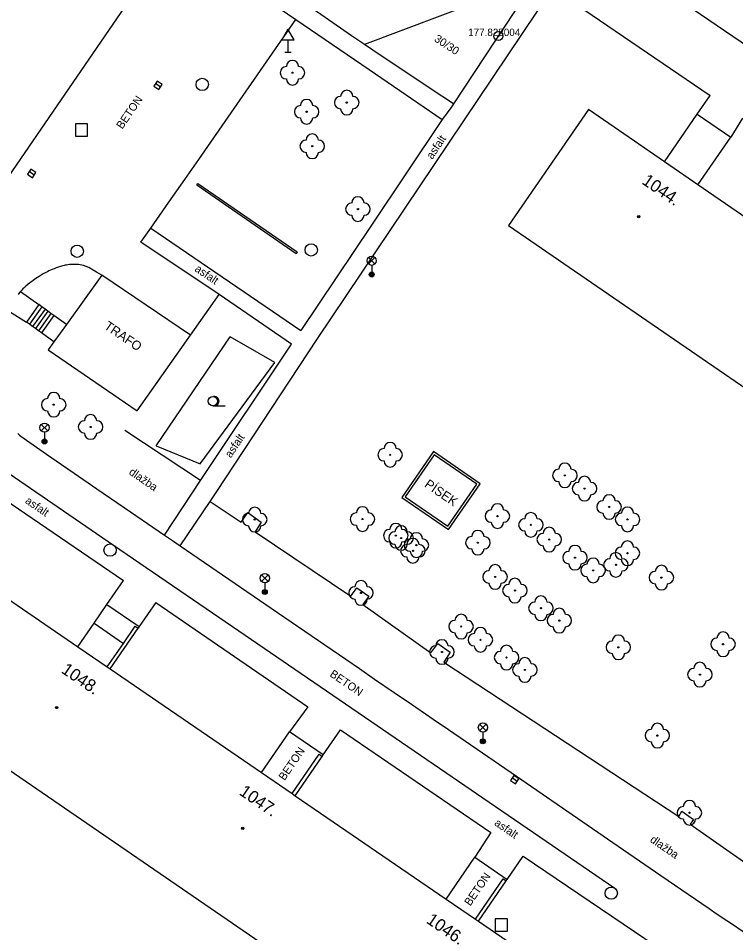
# Model space of a CAD drawing. Extents: x -539515 to -538098, y -1182060 to -1180157.
# Drawn here: x -538687.3 to -538629, y -1181340.3 to -1181266 of the extents above; entities that cross this region are included whole.
import ezdxf

# ---------------------------------------------------------------- set-up
doc = ezdxf.new("R2010")
doc.units = 0
for name, color, linetype in [('Vrstva 10', 7, 'Continuous'), ('Vrstva 11', 7, 'Continuous'), ('Vrstva 21', 7, 'Continuous'), ('Vrstva 22', 7, 'Continuous'), ('Vrstva 23', 7, 'Continuous'), ('Vrstva 26', 7, 'Continuous'), ('Vrstva 27', 7, 'Continuous'), ('Vrstva 33', 7, 'Continuous'), ('Vrstva 34', 7, 'Continuous'), ('Vrstva 36', 7, 'Continuous'), ('Vrstva 39', 7, 'Continuous'), ('Vrstva 40', 7, 'Continuous'), ('Vrstva 41', 7, 'Continuous'), ('Vrstva 47', 7, 'Continuous'), ('Vrstva 5', 7, 'Continuous'), ('Vrstva 7', 7, 'Continuous')]:
    doc.layers.add(name, color=color, linetype=linetype)

msp = doc.modelspace()

# ---------------------------------------------------------------- linework, layer by layer
at = {"layer": 'Vrstva 10'}
for p, q in [((-538634.64, -1181263.75), (-538621.575, -1181272.74)), ((-538672.638, -1181277.498), (-538664.76, -1181266.12)), ((-538670.97, -1181288.48), (-538677.35, -1181284.23)), ((-538673.32, -1181291.77), (-538670.97, -1181288.48)), ((-538696.576, -1181297.176), (-538679.57, -1181308.82)), ((-538653.55, -1181301.22), (-538656.129, -1181304.952)), ((-538653.499, -1181301.498), (-538655.851, -1181304.901)), ((-538649.76, -1181303.84), (-538653.55, -1181301.22)), ((-538650.037, -1181303.89), (-538653.499, -1181301.498)), ((-538652.338, -1181307.571), (-538649.76, -1181303.84)), ((-538652.389, -1181307.293), (-538650.037, -1181303.89)), ((-538656.129, -1181304.952), (-538652.338, -1181307.571)), ((-538655.851, -1181304.901), (-538652.389, -1181307.293)), ((-538679.57, -1181308.82), (-538669.384, -1181315.789)), ((-538674.15, -1181308.89), (-538666.245, -1181314.3)), ((-538669.384, -1181315.789), (-538654.102, -1181326.24)), ((-538654.102, -1181326.24), (-538638.82, -1181336.69)), ((-538646.81, -1181327.61), (-538638.982, -1181332.988))]:
    msp.add_line(p, q, dxfattribs=at)
for points in [[(-538677.35, -1181284.23), (-538676.944, -1181283.661), (-538676.54, -1181283.09), (-538675.059, -1181280.975), (-538673.766, -1181279.122), (-538672.638, -1181277.498)], [(-538680.53, -1181286.91), (-538680.944, -1181286.656), (-538681.358, -1181286.402), (-538681.432, -1181286.358), (-538681.505, -1181286.318), (-538681.578, -1181286.281), (-538681.651, -1181286.248), (-538681.723, -1181286.217), (-538681.795, -1181286.189), (-538681.866, -1181286.163), (-538681.937, -1181286.14), (-538682.007, -1181286.12), (-538682.147, -1181286.085), (-538682.284, -1181286.059), (-538682.418, -1181286.04), (-538682.549, -1181286.028), (-538682.677, -1181286.021), (-538682.802, -1181286.02), (-538682.924, -1181286.023), (-538683.043, -1181286.031), (-538683.159, -1181286.042), (-538683.272, -1181286.057), (-538683.382, -1181286.074), (-538683.488, -1181286.093), (-538683.592, -1181286.115), (-538683.692, -1181286.139), (-538683.79, -1181286.164), (-538683.884, -1181286.191), (-538684.067, -1181286.248), (-538684.239, -1181286.308), (-538684.4, -1181286.37), (-538684.551, -1181286.433), (-538684.692, -1181286.496), (-538684.824, -1181286.559), (-538684.947, -1181286.62), (-538685.062, -1181286.68), (-538685.276, -1181286.798), (-538685.461, -1181286.908), (-538685.622, -1181287.008), (-538685.761, -1181287.099), (-538685.882, -1181287.18), (-538686.09, -1181287.328), (-538686.244, -1181287.442), (-538686.358, -1181287.529), (-538686.526, -1181287.663), (-538686.69, -1181287.8), (-538686.756, -1181287.857), (-538686.817, -1181287.912), (-538686.931, -1181288.02), (-538687.031, -1181288.123), (-538687.119, -1181288.22), (-538687.198, -1181288.312), (-538687.267, -1181288.399), (-538687.33, -1181288.481)], [(-538687.358, -1181299.762), (-538687.297, -1181299.817), (-538687.2, -1181299.895), (-538687.1, -1181299.97), (-538686.371, -1181300.484), (-538685.004, -1181301.44), (-538683.808, -1181302.271), (-538682.761, -1181302.995)], [(-538682.761, -1181302.995), (-538680.927, -1181304.255), (-538678.175, -1181306.137), (-538675.42, -1181308.02), (-538674.785, -1181308.455)], [(-538674.785, -1181308.455), (-538674.15, -1181308.89)], [(-538666.245, -1181314.3), (-538659.578, -1181318.863)], [(-538659.578, -1181318.863), (-538658.34, -1181319.71)], [(-538658.34, -1181319.71), (-538656.752, -1181320.795), (-538655.345, -1181321.754), (-538653.847, -1181322.776), (-538653.589, -1181322.954), (-538652.35, -1181323.8)], [(-538652.35, -1181323.8), (-538649.579, -1181325.704), (-538646.81, -1181327.61)], [(-538638.982, -1181332.988), (-538635.067, -1181335.675), (-538631.15, -1181338.36)], [(-538631.15, -1181338.36), (-538630.571, -1181338.752), (-538629.7, -1181339.334), (-538629.264, -1181339.626), (-538628.83, -1181339.92), (-538624.923, -1181342.589)]]:
    msp.add_lwpolyline(points, dxfattribs=at)
at = {"layer": 'Vrstva 11'}
for p, q in [((-538669.745, -1181262.72), (-538664.76, -1181266.12)), ((-538645.21, -1181262.81), (-538648.565, -1181267.895)), ((-538642.6, -1181264.43), (-538636.84, -1181268.37)), ((-538650.31, -1181264.84), (-538659.17, -1181268.16)), ((-538664.76, -1181266.12), (-538658.8, -1181270.19)), ((-538648.565, -1181267.895), (-538651.92, -1181272.98)), ((-538636.84, -1181268.37), (-538631.08, -1181272.31)), ((-538658.8, -1181270.19), (-538652.84, -1181274.26)), ((-538632.114, -1181273.816), (-538631.08, -1181272.31)), ((-538652.84, -1181274.26), (-538658.59, -1181282.83)), ((-538628.43, -1181274.15), (-538629.4, -1181275.68)), ((-538658.59, -1181282.83), (-538664.34, -1181291.4)), ((-538676.54, -1181283.09), (-538664.34, -1181291.4)), ((-538687.119, -1181288.22), (-538685.64, -1181289.29)), ((-538665.1, -1181292.51), (-538670.97, -1181288.48)), ((-538685.64, -1181289.29), (-538686.64, -1181290.71)), ((-538685.382, -1181289.475), (-538686.396, -1181290.885)), ((-538685.138, -1181289.65), (-538686.152, -1181291.06)), ((-538688.02, -1181289.85), (-538686.64, -1181290.71)), ((-538684.895, -1181289.825), (-538685.909, -1181291.235)), ((-538684.651, -1181290), (-538685.665, -1181291.41)), ((-538684.408, -1181290.175), (-538685.422, -1181291.585)), ((-538672.49, -1181303.59), (-538678.657, -1181299.511)), ((-538690.92, -1181303.4), (-538678.77, -1181311.7)), ((-538671.707, -1181305.275), (-538669.196, -1181306.972)), ((-538668.06, -1181307.74), (-538660.29, -1181312.97)), ((-538658.81, -1181312.97), (-538659.291, -1181313.663)), ((-538680.104, -1181313.648), (-538677.475, -1181315.449)), ((-538676.14, -1181313.5), (-538663.78, -1181321.97)), ((-538659.291, -1181313.663), (-538653.78, -1181317.59)), ((-538652.73, -1181318.33), (-538633.61, -1181330.87)), ((-538663.78, -1181321.97), (-538665.27, -1181323.99)), ((-538661.13, -1181323.83), (-538648.91, -1181332.17)), ((-538667.542, -1181327.306), (-538665.27, -1181323.99)), ((-538662.527, -1181325.869), (-538665.27, -1181323.99)), ((-538632.69, -1181331.5), (-538606.03, -1181350.16)), ((-538648.91, -1181332.17), (-538650.2, -1181334.18)), ((-538652.533, -1181337.586), (-538650.2, -1181334.18)), ((-538650.2, -1181334.18), (-538647.568, -1181335.981)), ((-538646.28, -1181334.1), (-538634.05, -1181342.34))]:
    msp.add_line(p, q, dxfattribs=at)
for points in [[(-538660.213, -1181267.449), (-538661.123, -1181266.823), (-538662.712, -1181265.723), (-538665.09, -1181264.066), (-538666.279, -1181263.237), (-538667.47, -1181262.41)], [(-538663.02, -1181292.1), (-538643.94, -1181263.7)], [(-538651.92, -1181272.98), (-538653.735, -1181271.778), (-538656.458, -1181269.978), (-538657.816, -1181269.072), (-538658.494, -1181268.617), (-538659.17, -1181268.16), (-538660.213, -1181267.449)], [(-538651.92, -1181272.98), (-538652.031, -1181273.143), (-538652.13, -1181273.284), (-538652.309, -1181273.527), (-538652.579, -1181273.89), (-538652.711, -1181274.074), (-538652.84, -1181274.26)], [(-538683.401, -1181290.901), (-538684.408, -1181290.175), (-538684.651, -1181290), (-538684.895, -1181289.825), (-538685.138, -1181289.65), (-538685.382, -1181289.475), (-538685.64, -1181289.29)], [(-538684.415, -1181292.31), (-538685.422, -1181291.585), (-538685.665, -1181291.41), (-538685.909, -1181291.235), (-538686.152, -1181291.06), (-538686.396, -1181290.885), (-538686.64, -1181290.71)], [(-538672.49, -1181303.59), (-538665.1, -1181292.51)], [(-538671.17, -1181304.48), (-538663.02, -1181292.1)], [(-538675.42, -1181308.02), (-538672.49, -1181303.59)], [(-538674.15, -1181308.89), (-538671.707, -1181305.275), (-538671.17, -1181304.48)], [(-538669.196, -1181306.972), (-538668.66, -1181306.18), (-538667.56, -1181306.97), (-538668.06, -1181307.74)], [(-538681.15, -1181315.18), (-538680.104, -1181313.648), (-538678.77, -1181311.7)], [(-538660.29, -1181312.97), (-538659.79, -1181312.29), (-538658.81, -1181312.97)], [(-538676.14, -1181313.5), (-538677.475, -1181315.449), (-538677.56, -1181315.573)], [(-538653.78, -1181317.59), (-538653.21, -1181316.81), (-538652.19, -1181317.53), (-538652.73, -1181318.33)], [(-538662.611, -1181325.992), (-538662.527, -1181325.869), (-538661.13, -1181323.83)], [(-538633.61, -1181330.87), (-538633.36, -1181330.45), (-538632.41, -1181331.11), (-538632.69, -1181331.5)], [(-538647.653, -1181336.105), (-538647.568, -1181335.981), (-538646.28, -1181334.1)]]:
    msp.add_lwpolyline(points, dxfattribs=at)
at = {"layer": 'Vrstva 21'}
for p, q in [((-538676.09, -1181300.75), (-538670.086, -1181291.901)), ((-538666.46, -1181293.99), (-538670.086, -1181291.901)), ((-538672.53, -1181302.22), (-538666.46, -1181293.99)), ((-538676.09, -1181300.75), (-538672.53, -1181302.22))]:
    msp.add_line(p, q, dxfattribs=at)
for radius in [0.375, 0.375, 0.05, 0.05]:
    msp.add_circle((-538648.29, -1181267.47), radius, dxfattribs=at)
at = {"layer": 'Vrstva 22'}
for centre in [(-538665.02, -1181270.45), (-538660.61, -1181272.88), (-538663.87, -1181273.62), (-538663.41, -1181276.42), (-538659.7, -1181281.53), (-538684.43, -1181297.42), (-538681.43, -1181299.23), (-538657.08, -1181301.49), (-538642.88, -1181303.16), (-538641.28, -1181304.24), (-538639.28, -1181305.73), (-538668.09, -1181306.75), (-538659.33, -1181306.71), (-538648.36, -1181306.47), (-538637.787, -1181306.736), (-538645.64, -1181307.18), (-538656.62, -1181308.06), (-538656.19, -1181308.25), (-538654.95, -1181308.83), (-538649.95, -1181308.63), (-538644.15, -1181308.38), (-538655.23, -1181309.29), (-538637.79, -1181309.49), (-538642.055, -1181309.847), (-538638.73, -1181310.43), (-538640.58, -1181310.88), (-538648.548, -1181311.416), (-538635.03, -1181311.47), (-538659.45, -1181312.71), (-538646.94, -1181312.52), (-538644.822, -1181313.952), (-538643.33, -1181314.96), (-538651.311, -1181315.441), (-538649.74, -1181316.52), (-538638.53, -1181317.13), (-538630.02, -1181316.88), (-538652.87, -1181317.51), (-538647.62, -1181317.959), (-538646.13, -1181318.97), (-538631.9, -1181319.35), (-538635.36, -1181324.3), (-538632.75, -1181330.57)]:
    msp.add_circle(centre, 0.05, dxfattribs=at)
for centre, start, end in [((-538665.02, -1181269.95), 0, 180), ((-538665.52, -1181270.45), 90, 270), ((-538664.52, -1181270.45), 270, 90), ((-538665.02, -1181270.95), 180, 0), ((-538660.61, -1181272.38), 0, 180), ((-538663.87, -1181273.12), 0, 180), ((-538661.11, -1181272.88), 90, 270), ((-538660.11, -1181272.88), 270, 90), ((-538664.37, -1181273.62), 90, 270), ((-538663.37, -1181273.62), 270, 90), ((-538660.61, -1181273.38), 180, 0), ((-538663.87, -1181274.12), 180, 0), ((-538663.41, -1181275.92), 0, 180), ((-538663.91, -1181276.42), 90, 270), ((-538662.91, -1181276.42), 270, 90), ((-538663.41, -1181276.92), 180, 0), ((-538659.7, -1181281.03), 0, 180), ((-538660.2, -1181281.53), 90, 270), ((-538659.2, -1181281.53), 270, 90), ((-538659.7, -1181282.03), 180, 0), ((-538684.93, -1181297.42), 90, 270), ((-538684.43, -1181296.92), 0, 180), ((-538683.93, -1181297.42), 270, 90), ((-538684.43, -1181297.92), 180, 0), ((-538681.43, -1181298.73), 0, 180), ((-538681.93, -1181299.23), 90, 270), ((-538680.93, -1181299.23), 270, 90), ((-538681.43, -1181299.73), 180, 0), ((-538657.08, -1181300.99), 0, 180), ((-538657.58, -1181301.49), 90, 270), ((-538656.58, -1181301.49), 270, 90), ((-538657.08, -1181301.99), 180, 0), ((-538642.88, -1181302.66), 0, 180), ((-538643.38, -1181303.16), 90, 270), ((-538642.38, -1181303.16), 270, 90), ((-538642.88, -1181303.66), 180, 0), ((-538641.78, -1181304.24), 90, 270), ((-538641.28, -1181303.74), 0, 180), ((-538640.78, -1181304.24), 270, 90), ((-538641.28, -1181304.74), 180, 0), ((-538639.78, -1181305.73), 90, 270), ((-538639.28, -1181305.23), 0, 180), ((-538638.78, -1181305.73), 270, 90), ((-538668.09, -1181306.25), 0, 180), ((-538659.33, -1181306.21), 0, 180), ((-538648.86, -1181306.47), 90, 270), ((-538648.36, -1181305.97), 0, 180), ((-538647.86, -1181306.47), 270, 90), ((-538637.787, -1181306.236), 0, 180), ((-538668.59, -1181306.75), 90, 270), ((-538667.59, -1181306.75), 270, 90), ((-538659.83, -1181306.71), 90, 270), ((-538658.83, -1181306.71), 270, 90), ((-538646.14, -1181307.18), 90, 270), ((-538645.64, -1181306.68), 0, 180), ((-538645.14, -1181307.18), 270, 90), ((-538639.28, -1181306.23), 180, 0), ((-538638.287, -1181306.736), 90, 270), ((-538637.287, -1181306.736), 270, 90), ((-538668.09, -1181307.25), 180, 0), ((-538659.33, -1181307.21), 180, 0), ((-538656.62, -1181307.56), 0, 180), ((-538656.19, -1181307.75), 0, 180), ((-538648.36, -1181306.97), 180, 0), ((-538644.15, -1181307.88), 0, 180), ((-538637.787, -1181307.236), 180, 0), ((-538657.12, -1181308.06), 90, 270), ((-538656.69, -1181308.25), 90, 270), ((-538656.12, -1181308.06), 270, 90), ((-538655.23, -1181308.79), 0, 180), ((-538655.69, -1181308.25), 270, 90), ((-538654.95, -1181308.33), 0, 180), ((-538650.45, -1181308.63), 90, 270), ((-538649.95, -1181308.13), 0, 180), ((-538649.45, -1181308.63), 270, 90), ((-538645.64, -1181307.68), 180, 0), ((-538644.65, -1181308.38), 90, 270), ((-538643.65, -1181308.38), 270, 90), ((-538656.62, -1181308.56), 180, 0), ((-538656.19, -1181308.75), 180, 0), ((-538655.73, -1181309.29), 90, 270), ((-538655.45, -1181308.83), 90, 270), ((-538654.73, -1181309.29), 270, 90), ((-538654.45, -1181308.83), 270, 90), ((-538644.15, -1181308.88), 180, 0), ((-538642.055, -1181309.347), 0, 180), ((-538638.29, -1181309.49), 90, 270), ((-538637.79, -1181308.99), 0, 180), ((-538637.29, -1181309.49), 270, 90), ((-538654.95, -1181309.33), 180, 0), ((-538649.95, -1181309.13), 180, 0), ((-538642.555, -1181309.847), 90, 270), ((-538641.555, -1181309.847), 270, 90), ((-538638.73, -1181309.93), 0, 180), ((-538655.23, -1181309.79), 180, 0), ((-538648.548, -1181310.916), 0, 180), ((-538642.055, -1181310.347), 180, 0), ((-538641.08, -1181310.88), 90, 270), ((-538640.58, -1181310.38), 0, 180), ((-538640.08, -1181310.88), 270, 90), ((-538639.23, -1181310.43), 90, 270), ((-538637.79, -1181309.99), 180, 0), ((-538638.23, -1181310.43), 270, 90), ((-538635.03, -1181310.97), 0, 180), ((-538649.048, -1181311.416), 90, 270), ((-538648.048, -1181311.416), 270, 90), ((-538638.73, -1181310.93), 180, 0), ((-538635.53, -1181311.47), 90, 270), ((-538634.53, -1181311.47), 270, 90), ((-538659.45, -1181312.21), 0, 180), ((-538648.548, -1181311.916), 180, 0), ((-538646.94, -1181312.02), 0, 180), ((-538640.58, -1181311.38), 180, 0), ((-538635.03, -1181311.97), 180, 0), ((-538659.95, -1181312.71), 90, 270), ((-538658.95, -1181312.71), 270, 90), ((-538647.44, -1181312.52), 90, 270), ((-538646.44, -1181312.52), 270, 90), ((-538659.45, -1181313.21), 180, 0), ((-538646.94, -1181313.02), 180, 0), ((-538645.322, -1181313.952), 90, 270), ((-538644.822, -1181313.452), 0, 180), ((-538644.322, -1181313.952), 270, 90), ((-538643.33, -1181314.46), 0, 180), ((-538651.811, -1181315.441), 90, 270), ((-538651.311, -1181314.941), 0, 180), ((-538650.811, -1181315.441), 270, 90), ((-538644.822, -1181314.452), 180, 0), ((-538643.83, -1181314.96), 90, 270), ((-538642.83, -1181314.96), 270, 90), ((-538649.74, -1181316.02), 0, 180), ((-538643.33, -1181315.46), 180, 0), ((-538651.311, -1181315.941), 180, 0), ((-538650.24, -1181316.52), 90, 270), ((-538649.24, -1181316.52), 270, 90), ((-538638.53, -1181316.63), 0, 180), ((-538630.52, -1181316.88), 90, 270), ((-538630.02, -1181316.38), 0, 180), ((-538629.52, -1181316.88), 270, 90), ((-538653.37, -1181317.51), 90, 270), ((-538652.87, -1181317.01), 0, 180), ((-538652.37, -1181317.51), 270, 90), ((-538649.74, -1181317.02), 180, 0), ((-538647.62, -1181317.459), 0, 180), ((-538639.03, -1181317.13), 90, 270), ((-538638.03, -1181317.13), 270, 90), ((-538648.12, -1181317.959), 90, 270), ((-538647.12, -1181317.959), 270, 90), ((-538638.53, -1181317.63), 180, 0), ((-538630.02, -1181317.38), 180, 0), ((-538652.87, -1181318.01), 180, 0), ((-538647.62, -1181318.459), 180, 0), ((-538646.63, -1181318.97), 90, 270), ((-538646.13, -1181318.47), 0, 180), ((-538645.63, -1181318.97), 270, 90), ((-538631.9, -1181318.85), 0, 180), ((-538632.4, -1181319.35), 90, 270), ((-538631.4, -1181319.35), 270, 90), ((-538646.13, -1181319.47), 180, 0), ((-538631.9, -1181319.85), 180, 0), ((-538635.86, -1181324.3), 90, 270), ((-538635.36, -1181323.8), 0, 180), ((-538634.86, -1181324.3), 270, 90), ((-538635.36, -1181324.8), 180, 0), ((-538632.75, -1181330.07), 0, 180), ((-538633.25, -1181330.57), 90, 270), ((-538632.25, -1181330.57), 270, 90), ((-538632.75, -1181331.07), 180, 0)]:
    msp.add_arc(centre, 0.5, start, end, dxfattribs=at)
at = {"layer": 'Vrstva 26'}
for points in [[(-538682.67, -1181275.61), (-538681.67, -1181275.61), (-538681.67, -1181274.61), (-538682.67, -1181274.61)], [(-538648.54, -1181340.19), (-538647.54, -1181340.19), (-538647.54, -1181339.19), (-538648.54, -1181339.19)]]:
    msp.add_lwpolyline(points, close=True, dxfattribs=at)
at = {"layer": 'Vrstva 27'}
for p, q in [((-538675.744, -1181271.621), (-538676.156, -1181271.339)), ((-538686.014, -1181278.771), (-538686.426, -1181278.489)), ((-538646.753, -1181328.024), (-538647.165, -1181327.742))]:
    msp.add_line(p, q, dxfattribs=at)
for points in [[(-538675.602, -1181271.415), (-538676.015, -1181271.132), (-538676.298, -1181271.545), (-538675.885, -1181271.828)], [(-538685.872, -1181278.565), (-538686.285, -1181278.282), (-538686.568, -1181278.695), (-538686.155, -1181278.978)], [(-538646.611, -1181327.818), (-538647.024, -1181327.535), (-538647.307, -1181327.948), (-538646.894, -1181328.231)]]:
    msp.add_lwpolyline(points, close=True, dxfattribs=at)
for centre in [(-538672.35, -1181271.4), (-538682.52, -1181284.96), (-538663.5, -1181284.85), (-538679.853, -1181309.233), (-538639.103, -1181337.103)]:
    msp.add_circle(centre, 0.5, dxfattribs=at)
at = {"layer": 'Vrstva 33'}
for p, q in [((-538658.845, -1181285.99), (-538658.315, -1181285.46)), ((-538658.845, -1181285.46), (-538658.315, -1181285.99)), ((-538658.58, -1181286.1), (-538658.58, -1181286.85)), ((-538685.445, -1181299.55), (-538684.915, -1181299.02)), ((-538685.445, -1181299.02), (-538684.915, -1181299.55)), ((-538685.18, -1181299.66), (-538685.18, -1181300.41)), ((-538667.535, -1181311.78), (-538667.005, -1181311.25)), ((-538667.535, -1181311.25), (-538667.005, -1181311.78)), ((-538667.27, -1181311.89), (-538667.27, -1181312.64)), ((-538649.805, -1181323.91), (-538649.275, -1181323.38)), ((-538649.805, -1181323.38), (-538649.275, -1181323.91)), ((-538649.54, -1181324.02), (-538649.54, -1181324.77))]:
    msp.add_line(p, q, dxfattribs=at)
for centre, radius in [((-538658.58, -1181285.725), 0.375), ((-538658.58, -1181286.85), 0.2), ((-538658.58, -1181286.85), 0.145), ((-538658.58, -1181286.85), 0.0876), ((-538685.18, -1181299.285), 0.375), ((-538685.18, -1181300.41), 0.2), ((-538685.18, -1181300.41), 0.145), ((-538685.18, -1181300.41), 0.0876), ((-538667.27, -1181311.515), 0.375), ((-538667.27, -1181312.64), 0.2), ((-538667.27, -1181312.64), 0.145), ((-538667.27, -1181312.64), 0.0876), ((-538649.54, -1181323.645), 0.375), ((-538649.54, -1181324.77), 0.2), ((-538649.54, -1181324.77), 0.145), ((-538649.54, -1181324.77), 0.0876)]:
    msp.add_circle(centre, radius, dxfattribs=at)
at = {"layer": 'Vrstva 34'}
for p, q in [((-538665.389, -1181267.767), (-538665.389, -1181268.785)), ((-538665.639, -1181268.785), (-538665.139, -1181268.785))]:
    msp.add_line(p, q, dxfattribs=at)
msp.add_lwpolyline([(-538665.889, -1181267.767), (-538664.889, -1181267.767), (-538665.389, -1181266.901)], close=True, dxfattribs=at)
at = {"layer": 'Vrstva 36'}
msp.add_line((-538671.491, -1181297.51), (-538670.491, -1181297.51), dxfattribs=at)
msp.add_circle((-538671.491, -1181297.135), 0.375, dxfattribs=at)
msp.add_arc((-538671.366, -1181297.135), 0.375, 260.40593, 99.59406, dxfattribs=at)
at = {"layer": 'Vrstva 39'}
for centre, radius in [((-538636.878, -1181282.148), 0.09), ((-538636.878, -1181282.148), 0.0398), ((-538684.195, -1181322.024), 0.09), ((-538684.195, -1181322.024), 0.0398), ((-538669.062, -1181331.834), 0.09), ((-538669.062, -1181331.834), 0.0398)]:
    msp.add_circle(centre, radius, dxfattribs=at)
at = {"layer": 'Vrstva 5'}
for p, q in [((-538640.97, -1181273.45), (-538647.45, -1181282.86)), ((-538634.782, -1181277.7), (-538632.114, -1181273.816)), ((-538632.114, -1181273.816), (-538629.4, -1181275.68)), ((-538632.068, -1181279.564), (-538629.4, -1181275.68)), ((-538673.32, -1181291.77), (-538680.53, -1181286.91)), ((-538677.64, -1181297.93), (-538673.32, -1181291.77)), ((-538684.89, -1181292.97), (-538677.64, -1181297.93)), ((-538724.84, -1181301.89), (-538635.14, -1181363.33)), ((-538682.46, -1181317.088), (-538681.15, -1181315.18)), ((-538681.15, -1181315.18), (-538678.77, -1181316.81))]:
    msp.add_line(p, q, dxfattribs=at)
for points in [[(-538674.73, -1181259.32), (-538689.745, -1181281.25)], [(-538634.782, -1181277.7), (-538640.97, -1181273.45)], [(-538632.068, -1181279.564), (-538634.782, -1181277.7)], [(-538620.033, -1181287.83), (-538632.068, -1181279.564)], [(-538647.45, -1181282.86), (-538548.42, -1181350.836)], [(-538680.53, -1181286.91), (-538683.401, -1181290.901)], [(-538683.401, -1181290.901), (-538684.415, -1181292.31)], [(-538684.415, -1181292.31), (-538684.89, -1181292.97)], [(-538694.6, -1181308.773), (-538682.46, -1181317.088)], [(-538682.46, -1181317.088), (-538680.078, -1181318.719)], [(-538680.078, -1181318.719), (-538679.831, -1181318.889)], [(-538679.831, -1181318.889), (-538667.542, -1181327.306)], [(-538667.542, -1181327.306), (-538665.045, -1181329.015)], [(-538665.045, -1181329.015), (-538664.798, -1181329.185)], [(-538664.798, -1181329.185), (-538652.533, -1181337.586)], [(-538652.533, -1181337.586), (-538650.149, -1181339.218)], [(-538650.149, -1181339.218), (-538649.902, -1181339.388)], [(-538649.902, -1181339.388), (-538637.736, -1181347.722)]]:
    msp.add_lwpolyline(points, dxfattribs=at)
at = {"layer": 'Vrstva 7'}
for p, q in [((-538672.8, -1181279.57), (-538664.72, -1181285.13)), ((-538679.831, -1181318.889), (-538677.56, -1181315.573)), ((-538664.798, -1181329.185), (-538662.611, -1181325.992)), ((-538649.902, -1181339.388), (-538647.653, -1181336.105))]:
    msp.add_line(p, q, dxfattribs=at)
for points in [[(-538672.8, -1181279.57), (-538672.715, -1181279.446)], [(-538672.715, -1181279.446), (-538664.635, -1181285.006)], [(-538664.635, -1181285.006), (-538664.72, -1181285.13)], [(-538680.078, -1181318.719), (-538678.77, -1181316.81), (-538677.807, -1181315.404), (-538677.56, -1181315.573)], [(-538665.045, -1181329.015), (-538662.858, -1181325.823), (-538662.611, -1181325.992)], [(-538650.149, -1181339.218), (-538647.901, -1181335.935), (-538647.653, -1181336.105)]]:
    msp.add_lwpolyline(points, dxfattribs=at)

# ---------------------------------------------------------------- texts
at = {"layer": 'Vrstva 22'}
msp.add_text('177.82 ', height=0.6, dxfattribs=at).set_placement((-538650.741, -1181267.47))
at = {"layer": 'Vrstva 23'}
msp.add_text('8004', height=0.6, dxfattribs=at).set_placement((-538648.29, -1181267.47))
at = {"layer": 'Vrstva 40'}
for s, rotation, p in [('30/30', 326.55021, (-538653.558, -1181267.846)), ('BETON', 55.60171, (-538678.862, -1181275.081)), ('asfalt', 56.23685, (-538653.654, -1181277.53)), ('asfalt', 325.73936, (-538673.022, -1181286.521)), ('asfalt', 56.23685, (-538670.034, -1181301.793)), ('dlažba', 325.6045, (-538678.373, -1181303.027)), ('asfalt', 325.66194, (-538686.809, -1181305.365)), ('BETON', 325.63485, (-538662.046, -1181319.44)), ('BETON', 55.59526, (-538665.665, -1181328.001)), ('asfalt', 325.63535, (-538648.672, -1181331.535)), ('dlažba', 325.6045, (-538636.014, -1181332.889)), ('BETON', 55.59526, (-538650.571, -1181338.189))]:
    msp.add_text(s, height=0.65, rotation=rotation, dxfattribs=at).set_placement(p)
at = {"layer": 'Vrstva 41'}
for s, rotation, p in [('TRAFO', 325.62249, (-538680.4, -1181291.195)), ('PÍSEK', 325.35824, (-538654.352, -1181304.042))]:
    msp.add_text(s, height=0.75, rotation=rotation, dxfattribs=at).set_placement(p)
at = {"layer": 'Vrstva 47'}
for s, rotation, p in [('1044.', 325.51823, (-538636.687, -1181279.425)), ('1048.', 325.59081, (-538683.888, -1181319.14)), ('1047.', 325.59081, (-538669.42, -1181329.05)), ('1046.', 325.59081, (-538654.214, -1181339.466))]:
    msp.add_text(s, height=1, rotation=rotation, dxfattribs=at).set_placement(p)

doc.saveas('drawing.dxf')
